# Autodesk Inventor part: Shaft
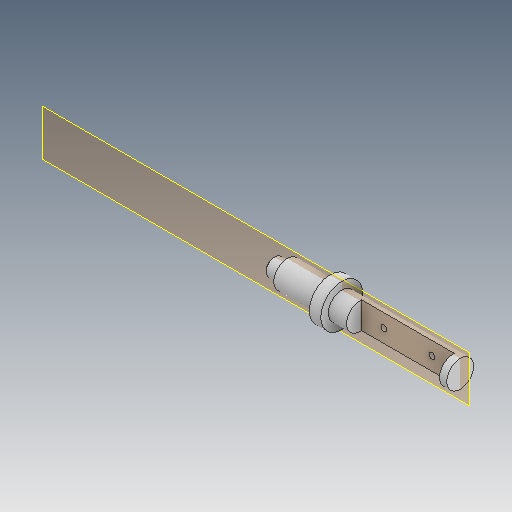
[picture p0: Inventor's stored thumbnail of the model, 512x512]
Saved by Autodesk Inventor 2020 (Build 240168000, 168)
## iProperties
Created: 2019-03
Part Number: Shaft
Material: Generic
Document SubType Name: Modeling
Designer: LENOVO-CADCIM
Density: 1 g/cm^3
Appearance: Default
Author: LENOVO-CADCIM
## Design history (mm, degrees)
sketch "Sketch1"
  geometry: L1 (284.311, 0)-(1023.188, 0); L2 (391.676, 0)-(391.676, -18); L3 (391.676, -18)-(420.576, -18); L4 (420.576, -18)-(420.576, -28); L5 (420.576, -28)-(510.376, -28); L6 (510.376, -28)-(510.376, -43.6); L7 (510.376, -43.6)-(534.376, -43.6); L8 (534.376, -43.6)-(534.376, -28); L9 (534.376, -28)-(781.476, -28); L10 (781.476, -28)-(781.476, 0); L11 (391.676, 0)-(781.476, 0); 1 further point
  constraints: 22 end point, 8 perpendicular, 5 point on line, 1 collinear, 1 horizontal
  dimensions: "d0" = 28.9 distance of L2.end L3.end; "d1" = 89.8 distance of L4.end L5.end; "d2" = 24 distance of L6.end L7.end; "d3" = 247.1 distance of L8.end L9.end; "d4" = 56 diameter of L9 L1; "d5" = 87.2 diameter of L7 L1; "d6" = 36 diameter of L3 L1
revolve "Revolution1" sketch "Sketch1" stored, may be unused: angle "d7" = 90 deg
sketch "Sketch4"
  geometry: L1 (-781.476, 28)-(-534.376, 28) reference; L2 (-572.576, 28)-(-766.376, 28); L3 (-766.376, 28)-(-766.376, -3.1); L4 (-766.376, -3.1)-(-572.576, -3.1); L5 (-572.576, -3.1)-(-572.576, 28); L6 (-781.476, -28)-(-534.376, -28) reference; 2 further points
  constraints: 8 end point, 2 parallel, 1 horizontal, 1 perpendicular, 1 point on line
  dimensions: "d16" = 24.9 distance between parallel lines of L6 L4; "d17" = 15.1 distance from line of L1.start L3; "d40" = 193.8 distance of L3.end L4.end
extrude "Extrusion3" cut sketch "Sketch4" stored distance "d18" = 257; taper "d19" = 0 deg
sketch "Sketch6"
  geometry: L1 (-180.9, 45.828)-(-180.9, 9.828) reference; L2 (-180.9, 27.828)-(320.546, 27.828); L3 (0, 55.828)-(0, -0.172) reference; 5 further points
  constraints: 2 end point, 2 point on line, 1 horizontal, 1 midpoint
  dimensions: "d24" = 100 distance of point (46.9, 27.828) point (146.9, 27.828); "d25" = 46.9 distance from line of L3 point (46.9, 27.828)
hole "Hole1" sketch "Sketch6" at (46.9, 27.828), (146.9, 27.828) diameter "d26" = 12.5; stored, may be unused: countersink angle "d30" = 90 deg, drill point angle "d32" = 118 deg; dims "d27" = 6, "d28" = 100, "d29" = 25, "d31" = 310
chamfer "Chamfer1" distance "d33" = 3; stored, may be unused: second distance "d34" = 2, angle "d35" = 45 deg
sketch "Sketch7"
  geometry: L1 (8, -22)-(-8, -22); L2 (-8, -22)-(-8, -26.833); L3 (8, -26.833)-(8, -22); L4 (0, 0)-(0, 64); C1 r 28 at (0, 0) reference; A1 r 28 centre (0, 0) between (-8, -26.833) and (8, -26.833); A2 r 28 centre (0, 0) between (8, -26.833) and (-8, -26.833) reference; 4 further points
  constraints: 8 end point, 3 point on circle, 1 centre point, 1 coincident, 1 concentric, 1 horizontal, 1 parallel, 1 perpendicular, 1 vertical, 1 other
  dimensions: "d36" = 16 distance between parallel lines of L3 L2; "d37" = 50 distance from line of point (0, 28) L1
extrude "Extrusion5" cut sketch "Sketch7" distance "d38" = 62.5; taper "d39" = 0 deg
body "Solid1"
